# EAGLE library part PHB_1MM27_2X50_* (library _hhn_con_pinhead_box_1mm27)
Pin Header Box-Type, 1.27mm/0.5"/50mil Pitch, 2x50 Circuits Note: see library description for an important note about THT-version
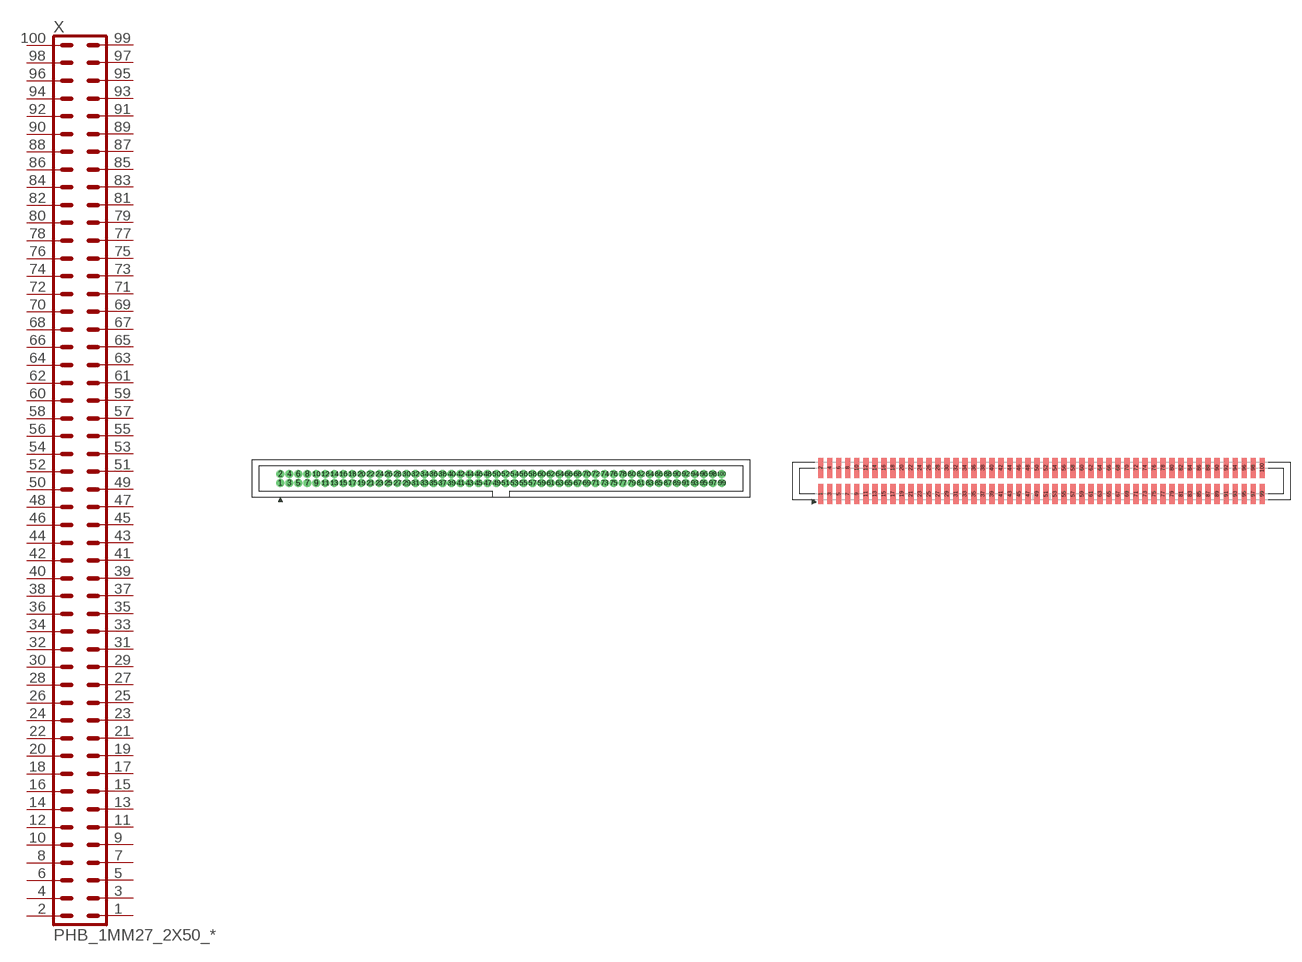
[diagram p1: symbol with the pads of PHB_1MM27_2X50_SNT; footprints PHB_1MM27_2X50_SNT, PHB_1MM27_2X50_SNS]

Designator prefix X

## PHB_1MM27_2X50_SNT  [PHB_1MM27_2X50_SNT]
1  1  pas
2  2  pas
3  3  pas
4  4  pas
5  5  pas
6  6  pas
7  7  pas
8  8  pas
9  9  pas
10  10  pas
11  11  pas
12  12  pas
13  13  pas
14  14  pas
15  15  pas
16  16  pas
17  17  pas
18  18  pas
19  19  pas
20  20  pas
21  21  pas
22  22  pas
23  23  pas
24  24  pas
25  25  pas
26  26  pas
27  27  pas
28  28  pas
29  29  pas
30  30  pas
31  31  pas
32  32  pas
33  33  pas
34  34  pas
35  35  pas
36  36  pas
37  37  pas
38  38  pas
39  39  pas
40  40  pas
41  41  pas
42  42  pas
43  43  pas
44  44  pas
45  45  pas
46  46  pas
47  47  pas
48  48  pas
49  49  pas
50  50  pas
51  51  pas
52  52  pas
53  53  pas
54  54  pas
55  55  pas
56  56  pas
57  57  pas
58  58  pas
59  59  pas
60  60  pas
61  61  pas
62  62  pas
63  63  pas
64  64  pas
65  65  pas
66  66  pas
67  67  pas
68  68  pas
69  69  pas
70  70  pas
71  71  pas
72  72  pas
73  73  pas
74  74  pas
75  75  pas
76  76  pas
77  77  pas
78  78  pas
79  79  pas
80  80  pas
81  81  pas
82  82  pas
83  83  pas
84  84  pas
85  85  pas
86  86  pas
87  87  pas
88  88  pas
89  89  pas
90  90  pas
91  91  pas
92  92  pas
93  93  pas
94  94  pas
95  95  pas
96  96  pas
97  97  pas
98  98  pas
99  99  pas
100  100  pas

## PHB_1MM27_2X50_SNS  [PHB_1MM27_2X50_SNS]
Pads as for PHB_1MM27_2X50_SNT

## Footprint PHB_1MM27_2X50_SNT (pad centres in mm)
Pin Header Box-Type, 1.27mm Pitch, 2x50 circuits, Straight, No Locking, THT Important Note: Diameter in this lbr is set to a specific value (NOT 'auto' = 0), this is ignored by actual eagle versions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
drill 0.65 pad 1 round: 1 -31.115,-0.635; 2 -31.115,0.635; 3 -29.845,-0.635; 4 -29.845,0.635; 5 -28.575,-0.635; 6 -28.575,0.635; 7 -27.305,-0.635; 8 -27.305,0.635; 9 -26.035,-0.635; 10 -26.035,0.635; 11 -24.765,-0.635; 12 -24.765,0.635; 13 -23.495,-0.635; 14 -23.495,0.635; 15 -22.225,-0.635; 16 -22.225,0.635; 17 -20.955,-0.635; 18 -20.955,0.635; 19 -19.685,-0.635; 20 -19.685,0.635; 21 -18.415,-0.635; 22 -18.415,0.635; 23 -17.145,-0.635; 24 -17.145,0.635; 25 -15.875,-0.635; 26 -15.875,0.635; 27 -14.605,-0.635; 28 -14.605,0.635; 29 -13.335,-0.635; 30 -13.335,0.635; 31 -12.065,-0.635; 32 -12.065,0.635; 33 -10.795,-0.635; 34 -10.795,0.635; 35 -9.525,-0.635; 36 -9.525,0.635; 37 -8.255,-0.635; 38 -8.255,0.635; 39 -6.985,-0.635; 40 -6.985,0.635; 41 -5.715,-0.635; 42 -5.715,0.635; 43 -4.445,-0.635; 44 -4.445,0.635; 45 -3.175,-0.635; 46 -3.175,0.635; 47 -1.905,-0.635; 48 -1.905,0.635; 49 -0.635,-0.635; 50 -0.635,0.635; 51 0.635,-0.635; 52 0.635,0.635; 53 1.905,-0.635; 54 1.905,0.635; 55 3.175,-0.635; 56 3.175,0.635; 57 4.445,-0.635; 58 4.445,0.635; 59 5.715,-0.635; 60 5.715,0.635; 61 6.985,-0.635; 62 6.985,0.635; 63 8.255,-0.635; 64 8.255,0.635; 65 9.525,-0.635; 66 9.525,0.635; 67 10.795,-0.635; 68 10.795,0.635; 69 12.065,-0.635; 70 12.065,0.635; 71 13.335,-0.635; 72 13.335,0.635; 73 14.605,-0.635; 74 14.605,0.635; 75 15.875,-0.635; 76 15.875,0.635; 77 17.145,-0.635; 78 17.145,0.635; 79 18.415,-0.635; 80 18.415,0.635; 81 19.685,-0.635; 82 19.685,0.635; 83 20.955,-0.635; 84 20.955,0.635; 85 22.225,-0.635; 86 22.225,0.635; 87 23.495,-0.635; 88 23.495,0.635; 89 24.765,-0.635; 90 24.765,0.635; 91 26.035,-0.635; 92 26.035,0.635; 93 27.305,-0.635; 94 27.305,0.635; 95 28.575,-0.635; 96 28.575,0.635; 97 29.845,-0.635; 98 29.845,0.635; 99 31.115,-0.635; 100 31.115,0.635

## Footprint PHB_1MM27_2X50_SNS (pad centres in mm)
Pin Header Box-Type, 1.27mm Pitch, 2x50 circuits, Straight, No Locking, SMT
smd 0.76 x 2.8: 1 -31.115,-1.85; 2 -31.115,1.85; 3 -29.845,-1.85; 4 -29.845,1.85; 5 -28.575,-1.85; 6 -28.575,1.85; 7 -27.305,-1.85; 8 -27.305,1.85; 9 -26.035,-1.85; 10 -26.035,1.85; 11 -24.765,-1.85; 12 -24.765,1.85; 13 -23.495,-1.85; 14 -23.495,1.85; 15 -22.225,-1.85; 16 -22.225,1.85; 17 -20.955,-1.85; 18 -20.955,1.85; 19 -19.685,-1.85; 20 -19.685,1.85; 21 -18.415,-1.85; 22 -18.415,1.85; 23 -17.145,-1.85; 24 -17.145,1.85; 25 -15.875,-1.85; 26 -15.875,1.85; 27 -14.605,-1.85; 28 -14.605,1.85; 29 -13.335,-1.85; 30 -13.335,1.85; 31 -12.065,-1.85; 32 -12.065,1.85; 33 -10.795,-1.85; 34 -10.795,1.85; 35 -9.525,-1.85; 36 -9.525,1.85; 37 -8.255,-1.85; 38 -8.255,1.85; 39 -6.985,-1.85; 40 -6.985,1.85; 41 -5.715,-1.85; 42 -5.715,1.85; 43 -4.445,-1.85; 44 -4.445,1.85; 45 -3.175,-1.85; 46 -3.175,1.85; 47 -1.905,-1.85; 48 -1.905,1.85; 49 -0.635,-1.85; 50 -0.635,1.85; 51 0.635,-1.85; 52 0.635,1.85; 53 1.905,-1.85; 54 1.905,1.85; 55 3.175,-1.85; 56 3.175,1.85; 57 4.445,-1.85; 58 4.445,1.85; 59 5.715,-1.85; 60 5.715,1.85; 61 6.985,-1.85; 62 6.985,1.85; 63 8.255,-1.85; 64 8.255,1.85; 65 9.525,-1.85; 66 9.525,1.85; 67 10.795,-1.85; 68 10.795,1.85; 69 12.065,-1.85; 70 12.065,1.85; 71 13.335,-1.85; 72 13.335,1.85; 73 14.605,-1.85; 74 14.605,1.85; 75 15.875,-1.85; 76 15.875,1.85; 77 17.145,-1.85; 78 17.145,1.85; 79 18.415,-1.85; 80 18.415,1.85; 81 19.685,-1.85; 82 19.685,1.85; 83 20.955,-1.85; 84 20.955,1.85; 85 22.225,-1.85; 86 22.225,1.85; 87 23.495,-1.85; 88 23.495,1.85; 89 24.765,-1.85; 90 24.765,1.85; 91 26.035,-1.85; 92 26.035,1.85; 93 27.305,-1.85; 94 27.305,1.85; 95 28.575,-1.85; 96 28.575,1.85; 97 29.845,-1.85; 98 29.845,1.85; 99 31.115,-1.85; 100 31.115,1.85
